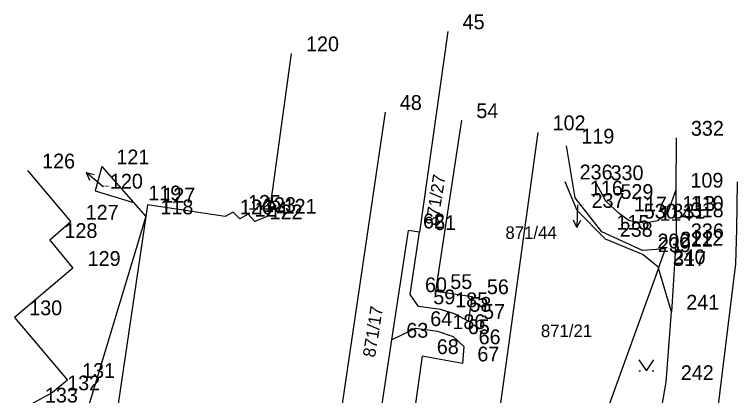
# Model space of a CAD drawing. Extents: x -822293 to -820259, y -1071573 to -1068794.
# Drawn here: x -821942.9 to -821844.9, y -1070017.3 to -1069965.7 of the extents above; entities that cross this region are included whole.
import ezdxf

# ---------------------------------------------------------------- set-up
doc = ezdxf.new("R2010")
doc.units = 0
for name, color, linetype in [('Vrstva 10', 7, 'Continuous'), ('Vrstva 2', 7, 'Continuous'), ('Vrstva 3', 7, 'Continuous'), ('Vrstva 4', 7, 'Continuous'), ('Vrstva 5', 7, 'Continuous'), ('Vrstva 7', 7, 'Continuous'), ('Vrstva 8', 7, 'Continuous'), ('Vrstva 9', 7, 'Continuous')]:
    doc.layers.add(name, color=color, linetype=linetype)

# ---------------------------------------------------------------- blocks, each defined once
blk = doc.blocks.new('Z314')
at = {"layer": 'Vrstva 2'}
for p, q in [((-100, 70), (0, -80)), ((0, -80), (100, 70)), ((-100, -80), (-80, -80)), ((80, -80), (100, -80))]:
    blk.add_line(p, q, dxfattribs=at)
blk = doc.blocks.new('Z61')
at = {"layer": 'Vrstva 2'}
for p, q in [((0, 300), (-50, 200)), ((0, 0), (0, 300)), ((0, 300), (50, 200))]:
    blk.add_line(p, q, dxfattribs=at)

msp = doc.modelspace()

# ---------------------------------------------------------------- linework, layer by layer
at = {"layer": 'Vrstva 2'}
for p, q in [((-821884.2, -1069968.03), (-821888.06, -1069995.21)), ((-821892.71, -1069978.95), (-821904.14, -1070056.55)), ((-821882.34, -1069980.05), (-821885.87, -1070003.19)), ((-821872, -1069981.7), (-821879.03, -1070032.47)), ((-821853.26, -1069982.44), (-821853.32, -1069989.47)), ((-821866.95, -1069990.53), (-821868.1, -1069983.5)), ((-821931.12, -1069986.32), (-821932, -1069989.6)), ((-821931.12, -1069986.32), (-821926.8, -1069991.2)), ((-821868.34, -1069988.36), (-821866.73, -1069992.21)), ((-821862.81, -1069991), (-821864.15, -1069988.46)), ((-821845.04, -1069994.8), (-821844.94, -1069988.4)), ((-821853.32, -1069989.47), (-821854.43, -1069992.62)), ((-821853.32, -1069989.47), (-821853.29, -1069992.58)), ((-821932, -1069989.6), (-821926.8, -1069991.2)), ((-821926.8, -1069991.2), (-821925.15, -1069993.08)), ((-821863.35, -1069995.16), (-821866.95, -1069990.53)), ((-821860.98, -1069992.69), (-821862.81, -1069991)), ((-821866.73, -1069992.21), (-821862.9, -1069996.12)), ((-821925.15, -1069993.08), (-821935.43, -1070027.08)), ((-821925.15, -1069993.08), (-821930.3, -1070027.86)), ((-821859.65, -1069993.66), (-821860.98, -1069992.69)), ((-821854.43, -1069992.62), (-821855.77, -1069993.66)), ((-821853.29, -1069992.58), (-821853.28, -1069993.48)), ((-821857.52, -1069993.96), (-821859.65, -1069993.66)), ((-821855.77, -1069993.66), (-821857.52, -1069993.96)), ((-821853.28, -1069993.48), (-821853.26, -1069996.32)), ((-821889.57, -1069994.99), (-821891.83, -1070009.78)), ((-821888.06, -1069995.21), (-821889.57, -1069994.99)), ((-821889.3, -1070003.62), (-821888.06, -1069995.21)), ((-821857.8, -1069997.7), (-821863.35, -1069995.16)), ((-821845.18, -1069999.48), (-821845.04, -1069994.8)), ((-821862.9, -1069996.12), (-821857.73, -1069998.2)), ((-821853.26, -1069996.32), (-821853.33, -1069997.33)), ((-821854.72, -1069997.44), (-821857.8, -1069997.7)), ((-821857.73, -1069998.2), (-821855.74, -1069999.83)), ((-821855.67, -1070000.07), (-821854.72, -1069997.44)), ((-821853.33, -1069997.33), (-821853.89, -1070005.98)), ((-821855.67, -1070000.07), (-821863.42, -1070021.56)), ((-821855.74, -1069999.83), (-821855.67, -1070000.07)), ((-821853.89, -1070005.98), (-821855.67, -1070000.07)), ((-821850.37, -1070042.01), (-821845.18, -1069999.48)), ((-821885.87, -1070003.19), (-821880.91, -1070003.89)), ((-821888.18, -1070005.26), (-821889.3, -1070003.62)), ((-821880.91, -1070003.89), (-821881.43, -1070007.24)), ((-821885.21, -1070005.66), (-821888.18, -1070005.26)), ((-821883.28, -1070006.27), (-821885.21, -1070005.66)), ((-821854.63, -1070015.52), (-821853.89, -1070005.98)), ((-821881.43, -1070007.24), (-821883.28, -1070006.27)), ((-821891.83, -1070009.78), (-821888.59, -1070008.21)), ((-821888.59, -1070008.21), (-821885.59, -1070008.62)), ((-821885.59, -1070008.62), (-821883.5, -1070009.3)), ((-821891.83, -1070009.78), (-821895.53, -1070033.91)), ((-821883.5, -1070009.3), (-821882.03, -1070010.67)), ((-821882.03, -1070010.67), (-821882.2, -1070012.99)), ((-821887.7, -1070012), (-821890.5, -1070032)), ((-821882.2, -1070012.99), (-821887.7, -1070012)), ((-821856.99, -1070029.49), (-821854.63, -1070015.52))]:
    msp.add_line(p, q, dxfattribs=at)
at = {"layer": 'Vrstva 3'}
for p, q in [((-821905.42, -1069971.01), (-821908.46, -1069993)), ((-821941.19, -1069986.87), (-821935.29, -1069993.8)), ((-821924.91, -1069991.49), (-821925.15, -1069993.08)), ((-821914.39, -1069993.08), (-821924.91, -1069991.49)), ((-821913.29, -1069992.47), (-821914.39, -1069993.08)), ((-821912.39, -1069993.39), (-821913.29, -1069992.47)), ((-821911.26, -1069992.77), (-821912.39, -1069993.39)), ((-821910.36, -1069993.76), (-821911.26, -1069992.77)), ((-821908.46, -1069993), (-821910.36, -1069993.76)), ((-821935.29, -1069993.8), (-821938.16, -1069996.28)), ((-821938.16, -1069996.28), (-821935.02, -1070000.06)), ((-821935.02, -1070000.06), (-821942.94, -1070006.74)), ((-821942.94, -1070006.74), (-821935.77, -1070015.23)), ((-821935.77, -1070015.23), (-821937.79, -1070016.9)), ((-821937.79, -1070016.9), (-821940.81, -1070018.56))]:
    msp.add_line(p, q, dxfattribs=at)
at = {"layer": 'Vrstva 4'}
msp.add_line((-821930.9, -1069989.08), (-821930.91, -1069989.07), dxfattribs=at)
at = {"layer": 'Vrstva 8'}
for p, q in [((-821884.2, -1069968.03), (-821884.2, -1069968.03)), ((-821905.42, -1069971.01), (-821905.42, -1069971.01)), ((-821892.71, -1069978.95), (-821892.71, -1069978.95)), ((-821882.34, -1069980.05), (-821882.34, -1069980.05)), ((-821872, -1069981.7), (-821872, -1069981.7)), ((-821853.26, -1069982.44), (-821853.26, -1069982.44)), ((-821868.1, -1069983.5), (-821868.1, -1069983.5)), ((-821931.12, -1069986.32), (-821931.12, -1069986.32)), ((-821941.19, -1069986.87), (-821941.19, -1069986.87)), ((-821868.34, -1069988.36), (-821868.34, -1069988.36)), ((-821864.15, -1069988.46), (-821864.15, -1069988.46)), ((-821844.94, -1069988.4), (-821844.94, -1069988.4)), ((-821853.32, -1069989.47), (-821853.32, -1069989.47)), ((-821932, -1069989.6), (-821932, -1069989.6)), ((-821926.8, -1069991.2), (-821926.8, -1069991.2)), ((-821866.95, -1069990.53), (-821866.95, -1069990.53)), ((-821862.81, -1069991), (-821862.81, -1069991)), ((-821924.91, -1069991.49), (-821924.91, -1069991.49)), ((-821866.73, -1069992.21), (-821866.73, -1069992.21)), ((-821925.15, -1069993.08), (-821925.15, -1069993.08)), ((-821914.39, -1069993.08), (-821914.39, -1069993.08)), ((-821913.29, -1069992.47), (-821913.29, -1069992.47)), ((-821912.39, -1069993.39), (-821912.39, -1069993.39)), ((-821911.26, -1069992.77), (-821911.26, -1069992.77)), ((-821908.46, -1069993), (-821908.46, -1069993)), ((-821860.98, -1069992.69), (-821860.98, -1069992.69)), ((-821854.43, -1069992.62), (-821854.43, -1069992.62)), ((-821853.29, -1069992.58), (-821853.29, -1069992.58)), ((-821935.29, -1069993.8), (-821935.29, -1069993.8)), ((-821910.36, -1069993.76), (-821910.36, -1069993.76)), ((-821859.65, -1069993.66), (-821859.65, -1069993.66)), ((-821857.52, -1069993.96), (-821857.52, -1069993.96)), ((-821855.77, -1069993.66), (-821855.77, -1069993.66)), ((-821853.28, -1069993.48), (-821853.28, -1069993.48)), ((-821889.57, -1069994.99), (-821889.57, -1069994.99)), ((-821888.06, -1069995.21), (-821888.06, -1069995.21)), ((-821863.35, -1069995.16), (-821863.35, -1069995.16)), ((-821845.04, -1069994.8), (-821845.04, -1069994.8)), ((-821938.16, -1069996.28), (-821938.16, -1069996.28)), ((-821862.9, -1069996.12), (-821862.9, -1069996.12)), ((-821853.26, -1069996.32), (-821853.26, -1069996.32)), ((-821857.8, -1069997.7), (-821857.8, -1069997.7)), ((-821857.73, -1069998.2), (-821857.73, -1069998.2)), ((-821854.72, -1069997.44), (-821854.72, -1069997.44)), ((-821853.33, -1069997.33), (-821853.33, -1069997.33)), ((-821935.02, -1070000.06), (-821935.02, -1070000.06)), ((-821855.74, -1069999.83), (-821855.74, -1069999.83)), ((-821855.67, -1070000.07), (-821855.67, -1070000.07)), ((-821845.18, -1069999.48), (-821845.18, -1069999.48)), ((-821885.87, -1070003.19), (-821885.87, -1070003.19)), ((-821889.3, -1070003.62), (-821889.3, -1070003.62)), ((-821880.91, -1070003.89), (-821880.91, -1070003.89)), ((-821888.18, -1070005.26), (-821888.18, -1070005.26)), ((-821885.21, -1070005.66), (-821885.21, -1070005.66)), ((-821853.89, -1070005.98), (-821853.89, -1070005.98)), ((-821942.94, -1070006.74), (-821942.94, -1070006.74)), ((-821883.28, -1070006.27), (-821883.28, -1070006.27)), ((-821881.43, -1070007.24), (-821881.43, -1070007.24)), ((-821888.59, -1070008.21), (-821888.59, -1070008.21)), ((-821885.59, -1070008.62), (-821885.59, -1070008.62)), ((-821891.83, -1070009.78), (-821891.83, -1070009.78)), ((-821883.5, -1070009.3), (-821883.5, -1070009.3)), ((-821882.03, -1070010.67), (-821882.03, -1070010.67)), ((-821887.7, -1070012), (-821887.7, -1070012)), ((-821882.2, -1070012.99), (-821882.2, -1070012.99)), ((-821935.77, -1070015.23), (-821935.77, -1070015.23)), ((-821854.63, -1070015.52), (-821854.63, -1070015.52)), ((-821937.79, -1070016.9), (-821937.79, -1070016.9))]:
    msp.add_line(p, q, dxfattribs=at)

# ---------------------------------------------------------------- block references
at = {"layer": 'Vrstva 10', "xscale": 0.01, "yscale": 0.01}
msp.add_blockref('Z314', (-821857.3, -1070013.17), dxfattribs=at)
at = {"layer": 'Vrstva 7', "yscale": 0.010000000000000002}
for p, xscale, rotation in [((-821930.91, -1069989.07), 0.01, 50.00000000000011), ((-821866.62, -1069991.57), 0.010000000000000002, 178.0000000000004)]:
    msp.add_blockref('Z61', p, dxfattribs=dict(at, xscale=xscale, rotation=rotation))

# ---------------------------------------------------------------- texts
at = {"layer": 'Vrstva 5'}
for s, p in [('871/27', (-821885.592, -1069994.398)), ('871/17', (-821894.072, -1070012.228))]:
    msp.add_text(s, height=1.7, rotation=81, dxfattribs=at).set_placement(p)
for s, height, p in [('871/14', 0.2, (-821930.9, -1069989.08)), ('871/44', 0.2, (-821866.62, -1069991.57)), ('871/21', 1.7, (-821871.593, -1070009.4))]:
    msp.add_text(s, height=height, dxfattribs=at).set_placement(p)
at = {"layer": 'Vrstva 7'}
msp.add_text('871/44', height=1.7, dxfattribs=at).set_placement((-821876.401, -1069996.11))
at = {"layer": 'Vrstva 9'}
for s, p in [('45', (-821882.2, -1069967.73)), ('120', (-821903.42, -1069970.71)), ('48', (-821890.71, -1069978.65)), ('54', (-821880.34, -1069979.75)), ('102', (-821870, -1069981.4)), ('332', (-821851.26, -1069982.14)), ('119', (-821866.1, -1069983.2)), ('126', (-821939.19, -1069986.57)), ('121', (-821929.12, -1069986.02)), ('236', (-821866.34, -1069988.06)), ('330', (-821862.15, -1069988.16)), ('120', (-821930, -1069989.3)), ('109', (-821851.32, -1069989.17)), ('116', (-821864.95, -1069990.23)), ('119', (-821924.8, -1069990.9)), ('127', (-821922.91, -1069991.19)), ('529', (-821860.81, -1069990.7)), ('125', (-821911.29, -1069992.17)), ('123', (-821909.26, -1069992.47)), ('237', (-821864.73, -1069991.91)), ('117', (-821858.98, -1069992.39)), ('113', (-821852.43, -1069992.32)), ('110', (-821851.29, -1069992.28)), ('118', (-821923.15, -1069992.78)), ('126', (-821912.39, -1069992.78)), ('124', (-821910.39, -1069993.09)), ('122', (-821908.36, -1069993.46)), ('121', (-821906.46, -1069992.7)), ('530', (-821857.65, -1069993.36)), ('331', (-821853.77, -1069993.36)), ('318', (-821851.28, -1069993.18)), ('127', (-821933.29, -1069993.5)), ('114', (-821855.52, -1069993.66)), ('62', (-821887.57, -1069994.69)), ('61', (-821886.06, -1069994.91)), ('115', (-821861.35, -1069994.86)), ('128', (-821936.16, -1069995.98)), ('238', (-821860.9, -1069995.82)), ('336', (-821851.26, -1069996.02)), ('222', (-821852.72, -1069997.14)), ('112', (-821851.33, -1069997.03)), ('200', (-821855.8, -1069997.4)), ('239', (-821855.73, -1069997.9)), ('129', (-821933.02, -1069999.76)), ('240', (-821853.74, -1069999.53)), ('317', (-821853.67, -1069999.77)), ('55', (-821883.87, -1070002.89)), ('60', (-821887.3, -1070003.32)), ('56', (-821878.91, -1070003.59)), ('59', (-821886.18, -1070004.96)), ('185', (-821883.21, -1070005.36)), ('58', (-821881.28, -1070005.97)), ('241', (-821851.89, -1070005.68)), ('130', (-821940.94, -1070006.44)), ('57', (-821879.43, -1070006.94)), ('64', (-821886.59, -1070007.91)), ('186', (-821883.59, -1070008.32)), ('65', (-821881.5, -1070009)), ('63', (-821889.83, -1070009.48)), ('66', (-821880.03, -1070010.37)), ('68', (-821885.7, -1070011.7)), ('67', (-821880.2, -1070012.69)), ('131', (-821933.77, -1070014.93)), ('242', (-821852.63, -1070015.22)), ('132', (-821935.79, -1070016.6)), ('133', (-821938.81, -1070018.26))]:
    msp.add_text(s, height=2, dxfattribs=at).set_placement(p)

doc.saveas('drawing.dxf')
